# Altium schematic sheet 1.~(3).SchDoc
size 420 x 297 mm
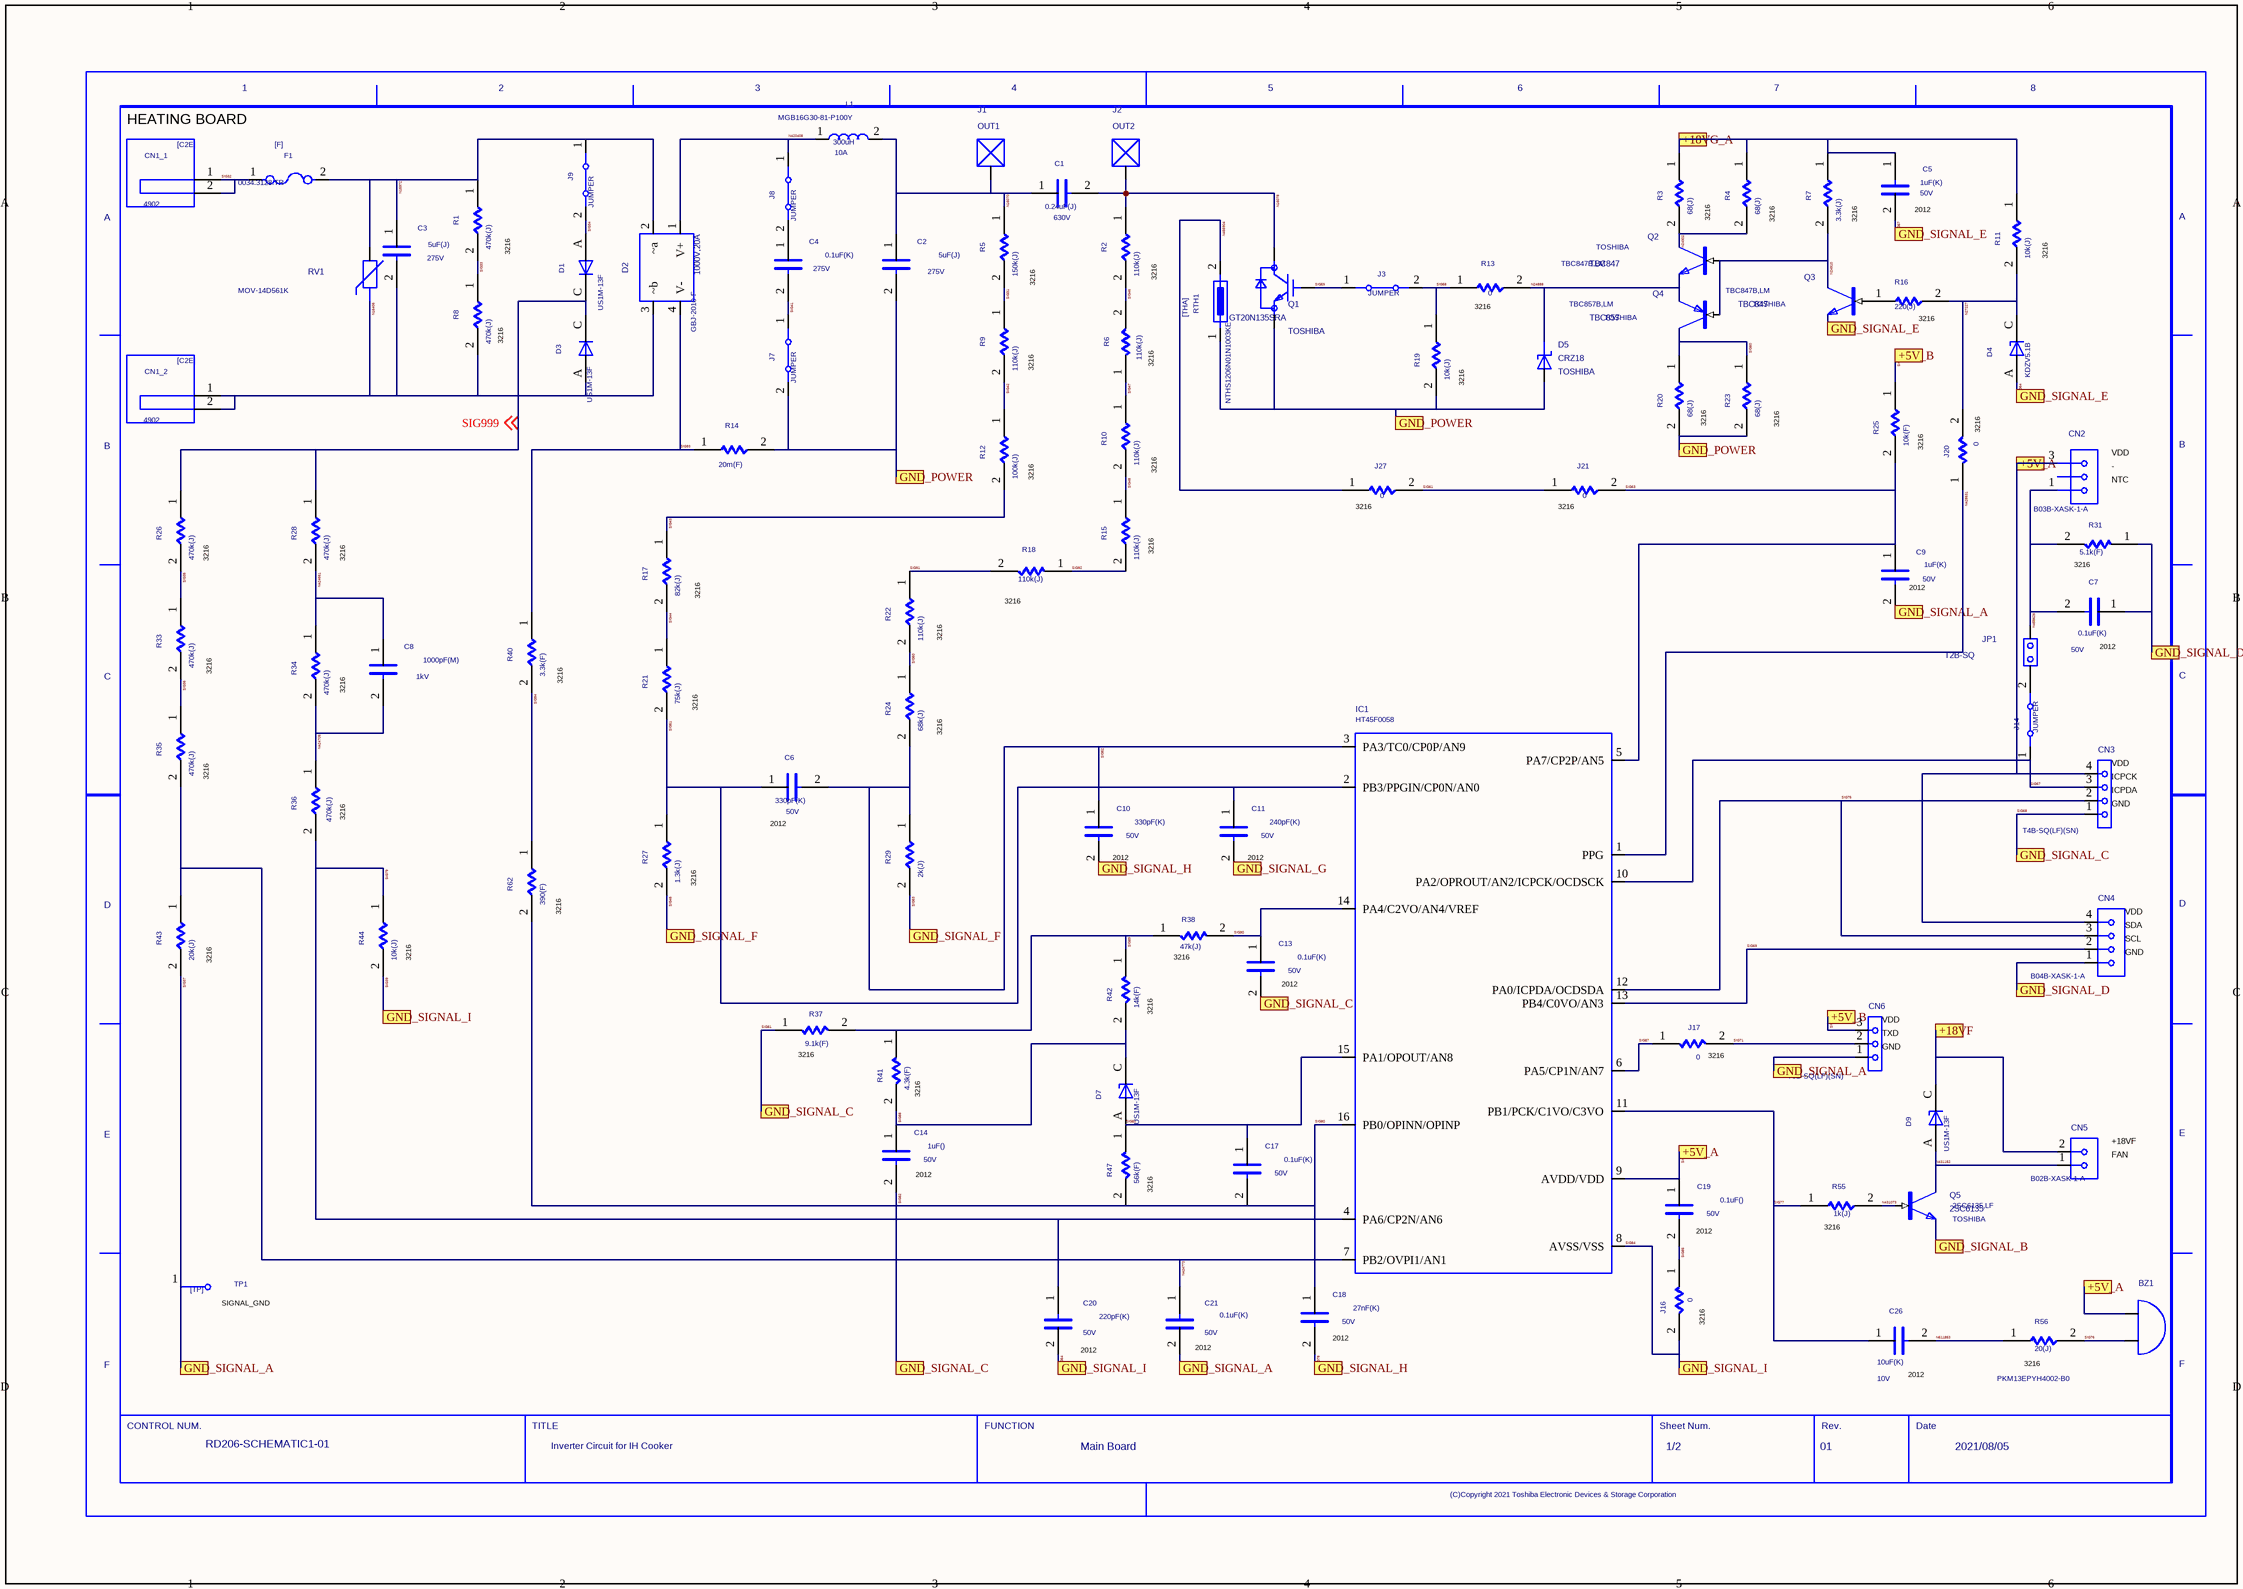
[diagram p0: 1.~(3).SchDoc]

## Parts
BZ1  PKM13EPYH4002-B0  [DIP]
C1  VAL2: 630V  VAL1: 0.24uF(J)  (hidden comment: C)
C2  VAL2: 275V  VAL1: 5uF(J)  (hidden comment: C)
C3  VAL2: 275V  VAL1: 5uF(J)  (hidden comment: C)
C4  VAL2: 275V  VAL1: 0.1uF(K)  (hidden comment: C)
C5  VAL2: 50V  VAL1: 1uF(K)  (hidden comment: C)
C6  VAL2: 50V  VAL1: 330pF(K)  (hidden comment: C)
C7  VAL2: 50V  VAL1: 0.1uF(K)  (hidden comment: C)
C8  VAL2: 1kV  VAL1: 1000pF(M)  (hidden comment: C)
C9  VAL2: 50V  VAL1: 1uF(K)  (hidden comment: C)
C10  VAL2: 50V  VAL1: 330pF(K)  (hidden comment: C)
C11  VAL2: 50V  VAL1: 240pF(K)  (hidden comment: C)
C13  VAL2: 50V  VAL1: 0.1uF(K)  (hidden comment: C)
C14  VAL2: 50V  VAL1: 1uF()  (hidden comment: C)
C17  VAL2: 50V  VAL1: 0.1uF(K)  (hidden comment: C)
C18  VAL2: 50V  VAL1: 27nF(K)  (hidden comment: C)
C19  VAL2: 50V  VAL1: 0.1uF()  (hidden comment: C)
C20  VAL2: 50V  VAL1: 220pF(K)  (hidden comment: C)
C21  VAL2: 50V  VAL1: 0.1uF(K)  (hidden comment: C)
C26  VAL2: 10V  VAL1: 10uF(K)  (hidden comment: C)
CN1_1  VAL3: 4902  (hidden comment: C2E)
CN1_2  VAL3: 4902  (hidden comment: C2E)
CN2  VAL3: B03B-XASK-1-A  (hidden comment: CON3S)
CN3  VAL3: T4B-SQ(LF)(SN)  [DIP]  (hidden comment: T4B-SQ)
CN4  B04B-XASK-1-A  [DIP]
CN5  B02B-XASK-1-A  [DIP]
CN6  VAL3: T3B-SQ(LF)(SN)  [DIP]  (hidden comment: T3B-SQ)
D1  VAL3: US1M-13F  (hidden comment: D)
D2  VALUE2: 1000V,20A  VAL3: GBJ-2010-F  [SMA]  (hidden comment: GBJ2010)
D3  VAL3: US1M-13F  (hidden comment: D)
D4  VAL3: KDZV5.1B  (hidden comment: ZD)
D5  CRZ18  MANUFACTURER: TOSHIBA  [S-FLAT]
D7  VAL3: US1M-13F  (hidden comment: ZD)
D9  VAL3: US1M-13F  (hidden comment: ZD)
F1  VAL3: 0034.3128.TR  (hidden comment: F)
IC1  HT45F0058
J1  OUT1
J2  OUT2
J3  VAL3: JUMPER  (hidden comment: JP)
J7  VAL3: JUMPER  (hidden comment: JP)
J8  VAL3: JUMPER  (hidden comment: JP)
J9  VAL3: JUMPER  (hidden comment: JP)
J14  VAL3: JUMPER  (hidden comment: JP)
J16  VAL1: 0  (hidden comment: R)
J17  VAL1: 0  (hidden comment: R)
J20  VAL1: 0  (hidden comment: R)
J21  VAL1: 0  (hidden comment: R)
J27  VAL1: 0  (hidden comment: R)
JP1  T2B-SQ  [DIP]
L1  VAL3: MGB16G30-81-P100Y  VAL2: 10A  VAL1: 300uH  (hidden comment: L)
Q1  GT20N135SRA  MANUFACTURER: TOSHIBA  [TO-247]
Q2  TBC847  USERCOMPTEXT3: TOSHIBA  VAL3: TBC847B,LM  [SOT-23]
Q3  TBC847  USERCOMPTEXT3: TOSHIBA  VAL3: TBC847B,LM  [SOT-23]
Q4  TBC857  USERCOMPTEXT3: TOSHIBA  VAL3: TBC857B,LM  [SOT-23]
Q5  2SC6135  USERCOMPTEXT3: TOSHIBA  VAL3: 2SC6135,LF  [SOT-323]
R1  VAL1: 470k(J)  (hidden comment: R)
R2  VAL1: 110k(J)  (hidden comment: R)
R3  VAL1: 68(J)  (hidden comment: R)
R4  VAL1: 68(J)  (hidden comment: R)
R5  VAL1: 150k(J)  (hidden comment: R)
R6  VAL1: 110k(J)  (hidden comment: R)
R7  VAL1: 3.3k(J)  (hidden comment: R)
R8  VAL1: 470k(J)  (hidden comment: R)
R9  VAL1: 110k(J)  (hidden comment: R)
R10  VAL1: 110k(J)  (hidden comment: R)
R11  VAL1: 10k(J)  (hidden comment: R)
R12  VAL1: 100k(J)  (hidden comment: R)
R13  VAL1: 0  (hidden comment: R)
R14  VAL1: 20m(F)  (hidden comment: R)
R15  VAL1: 110k(J)  (hidden comment: R)
R16  VAL1: 220(J)  (hidden comment: R)
R17  VAL1: 82k(J)  (hidden comment: R)
R18  VAL1: 110k(J)  (hidden comment: R)
R19  VAL1: 10k(J)  (hidden comment: R)
R20  VAL1: 68(J)  (hidden comment: R)
R21  VAL1: 75k(J)  (hidden comment: R)
R22  VAL1: 110k(J)  (hidden comment: R)
R23  VAL1: 68(J)  (hidden comment: R)
R24  VAL1: 68k(J)  (hidden comment: R)
R25  VAL1: 10k(F)  (hidden comment: R)
R26  VAL1: 470k(J)  (hidden comment: R)
R27  VAL1: 1.3k(J)  (hidden comment: R)
R28  VAL1: 470k(J)  (hidden comment: R)
R29  VAL1: 2k(J)  (hidden comment: R)
R31  VAL1: 5.1k(F)  (hidden comment: R)
R33  VAL1: 470k(J)  (hidden comment: R)
R34  VAL1: 470k(J)  (hidden comment: R)
R35  VAL1: 470k(J)  (hidden comment: R)
R36  VAL1: 470k(J)  (hidden comment: R)
R37  VAL1: 9.1k(F)  (hidden comment: R)
R38  VAL1: 47k(J)  (hidden comment: R)
R40  VAL1: 3.3k(F)  (hidden comment: R)
R41  VAL1: 4.3k(F)  (hidden comment: R)
R42  VAL1: 14k(F)  (hidden comment: R)
R43  VAL1: 20k(J)  (hidden comment: R)
R44  VAL1: 10k(J)  (hidden comment: R)
R47  VAL1: 56k(F)  (hidden comment: R)
R55  VAL1: 1k(J)  (hidden comment: R)
R56  VAL1: 20(J)  (hidden comment: R)
R62  VAL1: 390(F)  (hidden comment: R)
RTH1  VAL3: NTHS1206N01N1003KE  (hidden comment: THA)
RV1  VAL3: MOV-14D561K  (hidden comment: VARISTOR)
TP1  TP  (value not drawn)
U?  DATE: 2021/08/05  DRAWINGNUMBER: RD206-SCHEMATIC1-01  FUNCTION: Main Board  REVISION: 01  SHEETNUMBER: 1/2  TITLE: Inverter Circuit for IH Cooker  (hidden comment: WAKU_DEF100)

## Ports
+5V_A, +5V_B, +18VF, +18VG_A, GND_POWER, GND_SIGNAL_A, GND_SIGNAL_B, GND_SIGNAL_C, GND_SIGNAL_D, GND_SIGNAL_E, GND_SIGNAL_F, GND_SIGNAL_G, GND_SIGNAL_H, GND_SIGNAL_I

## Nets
+18VF: CN5.2 D9.C ; port +18VF
+18VG_A: C5.1 R3.1 R4.1 R7.1 R11.1 ; port +18VG_A
GND_POWER: C2.2 D5.A(Anode) J7.2 Q1.3(EMITTER) R14.2 R19.2 R20.2 R23.2 RTH1.1 ; port GND_POWER
GND_SIGNAL_B: Q5.2(E) ; port GND_SIGNAL_B
GND_SIGNAL_D: C7.1 CN4.1 R31.1 ; port GND_SIGNAL_D
GND_SIGNAL_G: C11.2 ; port GND_SIGNAL_G
N15972: C3.1 D2.2(~a) F1.2 J9.1 R1.1 RV1.1
N16070: C1.1 C2.1 J1.1 L1.2 R5.1
N16078: C1.2 J2.1 Q1.2(COLLECTOR) R2.1
N16406: C3.2 CN1_2.1 CN1_2.2 D2.3(~b) D3.A R8.2 RV1.2
N24888: D5.C(Cathode) Q2.2(E) Q4.2(E) R13.2
N24902: Q2.3(C) R3.2 R4.2
N24910: Q2.1(B) Q3.3(C) Q4.1(B) R7.2
N27227: D4.C J20.2 R11.2 R16.2
N420408: D2.1(V+) J8.1 L1.1
N424661: C8.1 R28.2 R34.1
N424705: C8.2 R34.2 R36.1
N424773: C21.1 IC1.7(PB2/OVPI1/AN1) R35.2 R43.1
N428631: IC1.1(PPG) J20.1
N431073: Q5.1(B) R55.2
N431152: CN5.1 D9.A Q5.3(C)
N456904: J27.1 RTH1.2
N458626: C7.2 CN2.1 JP1.2 R31.2
N611853: C26.2 R56.1
SIG31: R5.2 R9.1
SIG32: CN1_1.1 CN1_1.2 F1.1
SIG33: R1.2 R8.1
SIG34: D1.A J9.2
SIG35: R26.2 R33.1
SIG36: R33.2 R35.1
SIG37: C9.2 C21.2 CN6.1 R43.2 TP1.1 ; port GND_SIGNAL_A
SIG39: C20.2 IC1.8(AVSS/VSS) J16.2 R44.2 ; port GND_SIGNAL_I  [also labelled SIG54, SIG84]
SIG41: C4.2 J7.1
SIG42: R9.2 R12.1
SIG43: R12.2 R17.1
SIG44: R17.2 R21.1
SIG45: R27.2 R29.2 ; port GND_SIGNAL_F  [also labelled SIG53]
SIG46: R2.2 R6.2
SIG47: R6.1 R10.1
SIG48: R10.2 R15.1
SIG50: R22.2 R24.1
SIG51: C6.1 C11.1 IC1.2(PB3/PPGIN/CP0N/AN0) R21.2 R27.1
SIG52: C6.2 C10.1 IC1.3(PA3/TC0/CP0P/AN9) R24.2 R29.1
SIG57: C5.2 D4.A Q3.2(E) ; port GND_SIGNAL_E  [also labelled SIG64]
SIG58: J3.2 R13.1 R19.1
SIG59: J3.1 Q1.1(GATE)
SIG60: Q4.3(C) R20.1 R23.1
SIG61: J21.1 J27.2
SIG62: CN6.3 R25.1 ; port +5V_B  [also labelled SIG72]
SIG63: C9.1 IC1.5(PA7/CP2P/AN5) J21.2 R25.2
SIG67: CN3.3 IC1.10(PA2/OPROUT/AN2/ICPCK/OCDSCK) J14.1
SIG68: C13.2 C14.2 CN3.1 R37.1 ; port GND_SIGNAL_C  [also labelled SIG81, SIG82]
SIG69: CN4.2 IC1.13(PB4/C0VO/AN3)
SIG71: CN6.2 J17.2
SIG75: CN3.2 CN4.3 IC1.12(PA0/ICPDA/OCDSDA)
SIG76: BZ1.2 R56.2
SIG77: C26.1 IC1.11(PB1/PCK/C1VO/C3VO) R55.1
SIG78: C10.2 C18.2 ; port GND_SIGNAL_H
SIG79: C20.1 IC1.4(PA6/CP2N/AN6) R36.2 R44.1
SIG80: C17.2 C18.1 IC1.16(PB0/OPINN/OPINP) R47.2 R62.2
SIG83: C17.1 D7.A IC1.15(PA1/OPOUT/AN8) R47.1
SIG85: C19.2 J16.1
SIG86: BZ1.1 C19.1 CN2.3 CN3.4 CN4.4 IC1.9(AVDD/VDD) ; port +5V_A
SIG87: IC1.6(PA5/CP1N/AN7) J17.1
SIG88: C14.1 D7.C R41.2 R42.2
SIG89: R37.2 R38.1 R41.1 R42.1
SIG90: C13.1 IC1.14(PA4/C2VO/AN4/VREF) R38.2
SIG91: R18.2 R22.1
SIG92: R15.2 R18.1
SIG93: D2.4(V-) R14.1 R40.1
SIG94: R40.2 R62.1
SIG999: D1.C D3.C R26.1 R28.1 ; off-sheet SIG999
NetC4_1: C4.1 J8.2
NetJ14_2: J14.2 JP1.1
NetQ3_1: Q3.1(B) R16.1

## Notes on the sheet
- HEATING BOARD
- (near R1) 3216
- 3216
- (near R4) 3216
- (near C5) 2012
- (near R11) 3216
- (near R5) 3216
- (near R2) 3216
- (near R13) 3216
- (near R16) 3216
- (near R8) 3216
- (near R9) 3216
- (near R6) 3216
- (near R19) 3216
- (near R20) 3216
- (near R23) 3216
- (near J20) 3216
- VDD
- (near R12) 3216
- (near R10) 3216
- (near J27) 3216
- (near J21) 3216
- -
- NTC
- (near R26) 3216
- (near R28) 3216
- (near R17) 3216
- (near R15) 3216
- (near C9) 2012
- (near R31) 3216
- (near R22) 3216
- (near R18) 3216
- (near C7) 2012
- (near R33) 3216
- (near R40) 3216
- (near R21) 3216
- (near R24) 3216
- (near R35) 3216
- (near CN3) VDD
- (near CN3) ICPCK
- (near CN3) ICPDA
- (near R36) 3216
- (near C6) 2012
- (near C10) 2012
- (near C11) 2012
- (near CN3) GND
- (near R62) 3216
- (near R27) 3216
- (near CN4) VDD
- (near CN4) SDA
- (near R43) 3216
- (near R44) 3216
- (near R38) 3216
- (near C13) 2012
- (near CN4) GND
- (near CN4) SCL
- (near R37) 3216
- (near R42) 3216
- (near J17) 3216
- (near CN6) TXD
- (near CN6) GND
- (near CN6) VDD
- (near R41) 3216
- (near C14) 2012
- (near R47) 3216
- (near CN5) FAN
- (near CN5) +18VF
- (near C19) 2012
- (near R55) 3216
- (near TP1) SIGNAL_GND
- (near C18) 2012
- (near J16) 3216
- (near C20) 2012
- (near C21) 2012
- (near C26) 2012
- (near R56) 3216

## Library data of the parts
BZ1 = BUZZER: PARTNAME: Part13801; MANUFACTURER: Murata; TIME: 16:07:41; UPDATEUSER: t5459927; SAVECOUNT: 1; OriginalSymbolOrigin: (0,0); VALUE2: D12.6xH6.9,4kHz; INSTANCENAME: INS611789
C1 = C: PARTNAME: Part13608; OriginalSymbolOrigin: (2540,7620)
C2 C3 = C: PARTNAME: Part13609; OriginalSymbolOrigin: (2540,7620)
C4 = C: PARTNAME: Part13606; OriginalSymbolOrigin: (2540,7620)
C5 C20 C21 = C#1: PARTNAME: Part6003; OriginalSymbolOrigin: (2540,7620); CaptureCellPackProp: C##1
C6 C7 C9-C11 C13 C14 C17-C19 C26 = C: PARTNAME: Part6003; OriginalSymbolOrigin: (2540,7620)
C8 = C: PARTNAME: Part13607; OriginalSymbolOrigin: (2540,7620)
CN1_1 CN1_2 = C2E: PARTNAME: Part13901; SAVEAREA0: -4733,-209,25099,17942; TIME: 14:34:38; UPDATEUSER: fukuda-y; UPDATETIME: 16:35:06; SAVECOUNT: 10; OriginalSymbolOrigin: (5080,15240)
CN2 = CON3S: PARTNAME: Part13910; TIME: 16:07:41; UPDATEUSER: t5459927; UPDATETIME: 14:26:02; SAVECOUNT: 3; SAVEAREA0: -3803,-10405,11105,524; OriginalSymbolOrigin: (0,0)
CN3 = HEADER_4P: PARTNAME: Part13906; MANUFACTURER: JST; TIME: 16:07:41; UPDATEUSER: t5459927; SAVECOUNT: 1; SAVEAREA0: -6996,-12954,11642,710; OriginalSymbolOrigin: (0,0); VALUE2: for Debugger,(NM); INSTANCENAME: INS493247
CN4 = CON4S: PARTNAME: Part13904; MANUFACTURER: JST; TIME: 16:07:41; UPDATEUSER: t5459927; SAVECOUNT: 1; SAVEAREA0: -5711,-12954,12927,710; OriginalSymbolOrigin: (0,0); VALUE2: to DISPLAY BOARD; INSTANCENAME: INS493000
CN5 = CON2S: PARTNAME: Part13902; MANUFACTURER: JST; TIME: 16:07:41; UPDATEUSER: t5459927; SAVECOUNT: 1; SAVEAREA0: -1901,-7788,9280,409; OriginalSymbolOrigin: (0,0); VALUE2: to FAN; INSTANCENAME: INS493353
CN6 = HEADER_3P: PARTNAME: Part13908; MANUFACTURER: JST; TIME: 16:07:41; UPDATEUSER: t5459927; SAVECOUNT: 1; SAVEAREA0: -5093,-10384,9816,546; OriginalSymbolOrigin: (0,0); VALUE2: for UART Debug; INSTANCENAME: INS667453
D1 D3 = D: PARTNAME: Part13451; SAVEAREA0: -225,-91,12804,7836; SAVECOUNT: 3; TIME: 14:49:55; UPDATEUSER: 19870035; UPDATETIME: 14:20:16; OriginalSymbolOrigin: (5080,5080)
D2 = D25XB: PARTNAME: Part13452; MANUFACTURER: DIODES; TIME: 16:07:41; UPDATEUSER: t5459927; SAVECOUNT: 1; SAVEAREA0: -3247,-11751,15521,2008; OriginalSymbolOrigin: (0,0); INSTANCENAME: INS420197
D4 = ZD: PARTNAME: Part4291; SAVEAREA0: -4630,-153,17114,13055; TIME: 14:49:55; UPDATEUSER: fukuda-y; UPDATETIME: 08:18:42; SAVECOUNT: 6; OriginalSymbolOrigin: (5080,5080)
D5 = DIODE_ZENER: PARTNAME: Part4291; TIME: 16:07:41; UPDATEUSER: t5459927; SAVECOUNT: 1; OriginalSymbolOrigin: (0,0); INSTANCENAME: INS25179
D7 D9 = ZD: PARTNAME: Part13451; SAVEAREA0: -4630,-153,17114,13055; TIME: 14:49:55; UPDATEUSER: fukuda-y; UPDATETIME: 08:18:42; SAVECOUNT: 6; OriginalSymbolOrigin: (5080,5080)
F1 = F: PARTNAME: Part13701; OriginalSymbolOrigin: (2540,5080); VAL2: 12.5A 250VAC
IC1 = HT45F0058: PARTNAME: Part2183; MANUFACTURER: HOLTEK; TIME: 16:07:41; UPDATEUSER: t5459927; UPDATETIME: 09:12:11; SAVECOUNT: 2; SAVEAREA0: -96097,-76323,141060,32998; OriginalSymbolOrigin: (0,0)
J1 = TERMINAL: PARTNAME: Part13909; PART_NUMBER: for Heating coil; TIME: 16:07:41; UPDATEUSER: t5459927; SAVECOUNT: 1; SAVEAREA0: -3180,-7788,8001,409; OriginalSymbolOrigin: (0,0); INSTANCENAME: INS418589
J2 = TERMINAL: PARTNAME: Part13909; PART_NUMBER: for Heating coil; TIME: 16:07:41; UPDATEUSER: t5459927; SAVECOUNT: 1; SAVEAREA0: -3180,-7788,8001,409; OriginalSymbolOrigin: (0,0); VAL3: OUT1; INSTANCENAME: INS418681
J3 J7 J8 = JP: PARTNAME: Part13917; OriginalSymbolOrigin: (2540,5080)
J9 J14 = JP: PARTNAME: Part13915; OriginalSymbolOrigin: (2540,5080)
J16 J17 J20 J21 J27 R1-R13 R15-R29 R31 R33-R37 R40-R44 R47 R55 R56 R62 = R: PARTNAME: Part4004; OriginalSymbolOrigin: (5080,5080)
JP1 = HEADER: PARTNAME: Part13905; MANUFACTURER: JST; TIME: 16:07:41; UPDATEUSER: t5459927; SAVECOUNT: 1; SAVEAREA0: -2956,-6337,7768,1525; OriginalSymbolOrigin: (0,0); VAL3: T2B-SQ(LF)(SN); INSTANCENAME: INS520211
L1 = L: PARTNAME: Part13301; OriginalSymbolOrigin: (2540,5080)
Q1 = IGBT: PARTNAME: Part13501; TIME: 16:07:41; UPDATEUSER: t5459927; SAVECOUNT: 1; OriginalSymbolOrigin: (0,0); INSTANCENAME: INS24255
Q2 = 2SC: PARTNAME: Part5004; TIME: 16:07:41; UPDATEUSER: t5459927; SAVECOUNT: 1; OriginalSymbolOrigin: (0,2540); INSTANCENAME: INS24481
Q3 = 2SC: PARTNAME: Part5004; TIME: 16:07:41; UPDATEUSER: t5459927; SAVECOUNT: 1; OriginalSymbolOrigin: (0,2540); INSTANCENAME: INS24374
Q4 = 2SA: PARTNAME: Part5004; TIME: 16:07:41; UPDATEUSER: t5459927; SAVECOUNT: 1; OriginalSymbolOrigin: (0,2540); INSTANCENAME: INS24550
Q5 = 2SC: PARTNAME: Part13502; TIME: 16:07:41; UPDATEUSER: t5459927; SAVECOUNT: 1; OriginalSymbolOrigin: (0,2540); INSTANCENAME: INS429563
R14 = R: PARTNAME: Part13402; OriginalSymbolOrigin: (5080,5080)
R38 = R#1: PARTNAME: Part4004; OriginalSymbolOrigin: (5080,5080); CaptureCellPackProp: R##1
RTH1 = THA: PARTNAME: Part3109; SAVECOUNT: 3; SAVEAREA0: -562,-143,15615,10489; TIME: 16:37:29; UPDATEUSER: sato-yr; OriginalSymbolOrigin: (2540,5080)
RV1 = VARISTOR: PARTNAME: Part13302; TIME: 16:07:41; UPDATEUSER: t5459927; UPDATETIME: 09:40:33; SAVECOUNT: 2; SAVEAREA0: -22723,-23461,27592,13427; OriginalSymbolOrigin: (0,-2540)
TP1 = TP: PARTNAME: Part13998; TIME: 16:12:21; UPDATEUSER: fukuda-y; UPDATETIME: 16:18:11; SAVECOUNT: 2; SAVEAREA0: -242,-92,12810,7836; OriginalSymbolOrigin: (0,7620)
U? = WAKU_DEF100: PLOTTIME: HH:MM; SAVEAREA0: 148187,-66180,486823,89919; TIME: 14:30:25; UPDATEUSER: t5459927; UPDATETIME: 11:15:29; SAVECOUNT: 6; OriginalSymbolOrigin: (10160,284480)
